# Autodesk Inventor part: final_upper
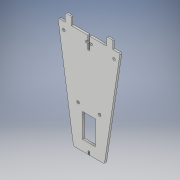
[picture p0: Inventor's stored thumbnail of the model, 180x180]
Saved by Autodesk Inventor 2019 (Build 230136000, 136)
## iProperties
Created: 2020-02
Part Number: final_upper
Material: Generic
Document SubType Name: Modeling
Designer: shivu
Density: 1 g/cm^3
Appearance: Default
Author: shivu
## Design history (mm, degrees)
sketch "Sketch1"
  geometry: L1 (0, 0)-(60, 0); L2 (60, 0)-(60, 100); L3 (60, 100)-(0, 100); L4 (0, 100)-(0, 0); L5 (30, 0)-(30, 12.489); L6 (30, 0)-(15, 0); L7 (0, 100)-(15, 0); L8 (15, 0)-(-38.098, -7.965); L9 (-38.098, -7.965)-(-53.098, 92.035); L10 (-53.098, 92.035)-(0, 100); L11 (30, 12.489)-(30, 132.489); L12 (30, 0)-(45, 0); L13 (60, 100)-(45, 0); L14 (45, 0)-(119.062, -11.109); L15 (119.062, -11.109)-(134.062, 88.891); L16 (134.062, 88.891)-(60, 100)
  constraints: 32 end point, 6 parallel, 3 perpendicular, 2 point on line, 2 vertical, 1 horizontal, 1 midpoint
  dimensions: "d0" = 60 distance of L3.end L2.end; "d1" = 100 distance of L2.end L1.end; "d2" = 15 distance of L5.start L6.end; "d3" = 120 distance of L5.end L11.end; "d4" = 15 distance of L5.start L12.end
extrude "Extrusion1" new body sketch "Sketch1" distance "d5" = 2; taper "d6" = 0 deg
sketch "Sketch2"
  geometry: L1 (15, 0)-(45, 0) reference
sketch "Sketch3"
  geometry: L1 (15, 0)-(45, 0) reference; L2 (30, 0)-(30, 10); L3 (30, 10)-(23.8, 10); L4 (23.8, 10)-(23.8, 33.4); L5 (23.8, 33.4)-(30, 33.4); L6 (30, 33.4)-(30, 10); L7 (36.2, 33.4)-(30, 33.4); L8 (36.2, 10)-(36.2, 33.4); L9 (30, 10)-(36.2, 10); C1 r 1.25 at (19.547, 38.938); C2 r 1.25 at (40.453, 38.938); 1 further point
  constraints: 16 end point, 3 symmetric about line, 2 centre point, 2 parallel, 1 horizontal, 1 midpoint, 1 perpendicular, 1 vertical, 1 other
  dimensions: "d8" = 10 distance of L2.start L2.end; "d9" = 6.2 distance of L4.end L5.end; "d10" = 23.4 distance of L3.end L4.end; "d11" = 2.5 diameter of C1; "d12" = 5.5382 vertical distance of L4.end C1.centre
extrude "Extrusion2" cut sketch "Sketch3" distance "d13" = 10; taper "d14" = 0 deg
node "Sketch4"
sketch "Sketch6"
  geometry: L1 (0, 100)-(7, 100); L2 (7, 100)-(13, 100); L3 (13, 100)-(13, 108); L4 (13, 108)-(7, 108); L5 (7, 108)-(7, 100); L6 (45, 0)-(60, 100) reference; L7 (60, 100)-(53, 100); L8 (60, 100)-(0, 100) reference; L9 (53, 100)-(47, 100); L10 (47, 100)-(47, 108); L11 (47, 108)-(53, 108); L12 (53, 108)-(53, 100); 1 further point
  constraints: 20 end point, 4 parallel, 3 horizontal, 2 perpendicular, 1 point on line
  dimensions: "d15" = 7 distance of L1.start L1.end; "d16" = 6 distance of L4.end L3.end; "d17" = 8 distance of L3.end L2.end; "d18" = 7 distance of L6.end L7.end; "d19" = 6 distance of L10.end L11.end; "d20" = 8 distance of L9.end L10.end
extrude "Extrusion3" join sketch "Sketch6" distance "d21" = 1.5; taper "d22" = 0 deg
sketch "Sketch8"
  geometry: L1 (15, 0)-(45, 0) reference; L2 (47, 100)-(13, 100) reference; L3 (30, 100)-(29, 100); L4 (29, 100)-(29, 95); L5 (29, 95)-(27, 95); L6 (27, 95)-(27, 93); L7 (27, 93)-(29, 93); L8 (29, 93)-(29, 88); L9 (29, 88)-(30, 88); L10 (30, 100)-(31, 100); L11 (31, 100)-(31, 95); L12 (31, 95)-(33, 95); L13 (33, 95)-(33, 93); L14 (33, 93)-(31, 93); L15 (31, 93)-(31, 88); L16 (31, 88)-(30, 88); C1 r 1.25 at (5.65, 92.686); C2 r 1.25 at (54.35, 92.686); 1 further point
  constraints: 28 end point, 5 point on line, 3 perpendicular, 2 centre point, 1 midpoint
  dimensions: "d25" = 2.5 diameter of C1
extrude "Extrusion4" cut sketch "Sketch8" distance "d31" = 2; taper "d32" = 0 deg
sketch "Sketch10"
  geometry: L1 (23.8, 33.4)-(36.2, 33.4) reference; L2 (36.2, 10)-(23.8, 10) reference; L3 (23.8, 10)-(23.8, 33.4) reference; L4 (29.25, 28.907)-(29.25, 30.407); L5 (30.75, 28.907)-(30.75, 30.407); L6 (30.75, 30.407)-(29.25, 30.407); L7 (30.75, 0.193)-(29.25, 0.193); L8 (29.25, 1.693)-(29.25, 0.193); L9 (30.75, 1.693)-(30.75, 0.193); A1 r 1 centre (30, 28.245) between (29.25, 28.907) and (30.75, 28.907); A2 r 1 centre (30, 2.355) between (30.75, 1.693) and (29.25, 1.693); 1 further point
  constraints: 12 end point, 4 point on circle, 2 centre point, 2 vertical
extrude "Extrusion5" cut sketch "Sketch10" distance "d36" = 2; taper "d37" = 0 deg
fillet "Fillet1" dims "d38" = 1
body "Solid1"
